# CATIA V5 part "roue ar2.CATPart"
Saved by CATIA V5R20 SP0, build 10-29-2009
Part number: roue ar2
Bounding box of the stored display mesh (mm): x 225 to 275, y 180 to 260, z 0.01 to 79.99
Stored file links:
  D:\Dropbox\Pack 1 sylvain\mmoreau\mmoreau\mmoreau\fin\roue ar2.CATPart
  U:\think motion\fin\think motion2.CATProduct
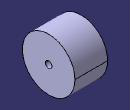
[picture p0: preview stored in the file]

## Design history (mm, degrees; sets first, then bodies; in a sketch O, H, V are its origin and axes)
Set1
  Plane1: linked copy from another document
  Point1: linked copy from another document
Body1 (main body)
  Sketch1 on Plane1, origin (225, 0, 0), H (0, 1, 0), V (0, 0, 1)
    circle A1 centre (220, 40) radius 40
    point P1 (220, 40)
    reference projected point E1 (220, 40) from Point1
    circle A2 centre (220, 40) radius 5
    point P2 (220, 40)
    reference projected point E2 (220, 40) from Point1
    radius A2 = 5
    coincidence: E1 P1, P2 E2
    tangency: A1 H
  Pad1: profile Sketch1, direction (1, 0, 0), length 50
